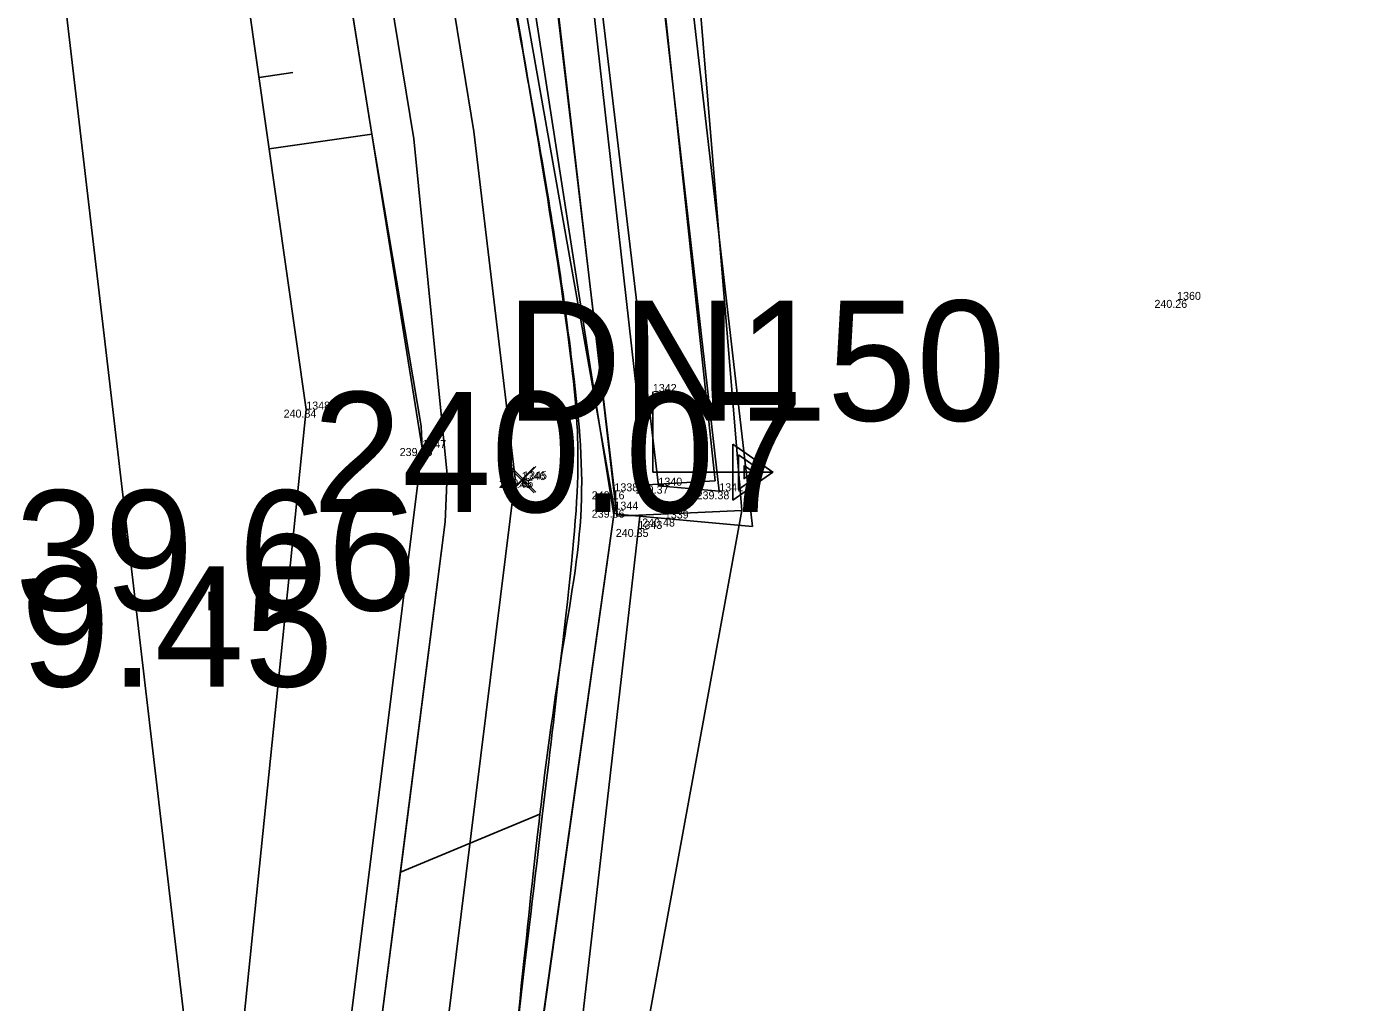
# Model space of a CAD drawing. Extents: x -555757 to -553364, y -1100723 to -1096439.
# Drawn here: x -553905.06 to -553888.24, y -1098914.94 to -1098902.76 of the extents above; entities that cross this region are included whole.
import ezdxf

# ---------------------------------------------------------------- set-up
doc = ezdxf.new("R2010")
doc.units = 0
for name, color, linetype in [('00_NÁVRH - 0.18 mm', 7, 'Continuous'), ('00_NÁVRH - 0.35 mm', 7, 'Continuous'), ('01_HLADINA', 7, 'Continuous'), ('Geodet. výšky - netisknuté', 7, 'Continuous'), ('HRANA$SVAHU', 7, 'Continuous'), ('HRANICE$PARCELY', 7, 'Continuous'), ('OSA$KOLEJI', 7, 'Continuous'), ('POPIS', 7, 'Continuous'), ('ROZHRANI', 7, 'Continuous'), ('SLUCKOV$$C$RA', 7, 'Continuous'), ('VODOVODY', 7, 'Continuous'), ('VYSKA_PODR_BOD', 7, 'Continuous'), ('VYSKOVE$SRAFY', 7, 'Continuous')]:
    doc.layers.add(name, color=color, linetype=linetype)

# ---------------------------------------------------------------- blocks, each defined once
blk = doc.blocks.new('POINT_DISPLAY')
blk.add_line((0, 0), (0, 0))
blk = doc.blocks.new('6$18')
at = {"layer": 'VODOVODY'}
for points in [[(0, 0), (0, -1), (1.5, -1)], [(1, -0.65), (1.5, -1), (1, -1.35), (1, -0.65)], [(1.07, -0.784), (1.378, -1), (1.07, -1.216), (1.07, -0.784)], [(1.14, -0.919), (1.256, -1), (1.14, -1.081), (1.14, -0.919)]]:
    blk.add_lwpolyline(points, dxfattribs=at)
blk = doc.blocks.new('BOD')
at = {"layer": 'POPIS'}
for p, q in [((-0.283, -0.283), (0.283, 0.283)), ((-0.283, 0.283), (0.283, -0.283))]:
    blk.add_line(p, q, dxfattribs=at)

msp = doc.modelspace()

# ---------------------------------------------------------------- linework, layer by layer
at = {"layer": '00_NÁVRH - 0.18 mm'}
for points in [[(-553947.788, -1099059.867), (-553935.377, -1099023.057), (-553925.589, -1098992.79), (-553914.105, -1098963.191), (-553902.24, -1098933.344), (-553901.606, -1098931.236), (-553900.811, -1098923.295), (-553898.96, -1098908.4), (-553899.478, -1098904.068), (-553900.725, -1098896.414), (-553901.4, -1098893.009), (-553901.337, -1098892.395), (-553901.104, -1098891.732), (-553884.458, -1098847.1)], [(-553942.062, -1099038.894), (-553935.99, -1099021.39), (-553928.935, -1098999.055), (-553926.84, -1098992.42), (-553922.458, -1098981.249), (-553916.003, -1098964.794), (-553911.939, -1098954.641), (-553909.255, -1098947.965), (-553903.25, -1098933.03), (-553903.005, -1098931.069), (-553900.12, -1098908.02), (-553900.136, -1098907.747), (-553900.75, -1098904.102), (-553902.469, -1098893.4), (-553902.5, -1098893.21), (-553902.5, -1098893.068), (-553902.439, -1098892.634), (-553902.302, -1098891.969), (-553902.077, -1098891.359), (-553899.834, -1098885.815), (-553893.94, -1098869.465), (-553889.919, -1098858.311), (-553887.458, -1098851.483), (-553885.715, -1098847.041)], [(-553946.39, -1099060.4), (-553933.906, -1099022.123), (-553924.31, -1098993.07), (-553913.795, -1098965.669), (-553901.23, -1098933.66), (-553900.818, -1098932.295), (-553900.55, -1098930.248), (-553899.67, -1098922.683), (-553897.726, -1098908.854), (-553898.025, -1098907), (-553899.515, -1098897.363), (-553900.336, -1098892.804), (-553883.522, -1098847.603)]]:
    msp.add_lwpolyline(points, dxfattribs=at)
at = {"layer": '00_NÁVRH - 0.35 mm'}
msp.add_lwpolyline([(-553948.493, -1099059.649), (-553935.545, -1099021.547), (-553926.445, -1098992.805), (-553915.734, -1098964.901), (-553914.927, -1098962.877), (-553903.079, -1098933.316), (-553902.406, -1098931.069), (-553901.65, -1098923.129), (-553899.834, -1098908.942), (-553899.809, -1098908.35), (-553900.227, -1098904.159), (-553901.487, -1098896.471), (-553902.129, -1098893.305), (-553902.102, -1098892.809), (-553902.038, -1098892.321), (-553901.906, -1098891.856), (-553885.171, -1098847.041)], dxfattribs=at)
msp.add_open_spline([(-553794.11, -1099299.314), (-553795.302, -1099298.083), (-553795.885, -1099297.697), (-553798.014, -1099296.378), (-553798.648, -1099296.009), (-553799.057, -1099295.868), (-553800.013, -1099295.626), (-553800.97, -1099295.434), (-553803.916, -1099294.978), (-553807.943, -1099294.404), (-553820.006, -1099292.714), (-553824.218, -1099292.087), (-553827.541, -1099291.556), (-553834.292, -1099290.18), (-553840, -1099289.072), (-553843.606, -1099288.311), (-553846.032, -1099287.854), (-553848.004, -1099287.449), (-553849.388, -1099287.281), (-553865.944, -1099285.252), (-553871.048, -1099284.805), (-553873.856, -1099284.514), (-553874.399, -1099284.43), (-553876.775, -1099283.969), (-553879.064, -1099283.332), (-553880.051, -1099283.031), (-553881.093, -1099282.392), (-553882.188, -1099281.754), (-553883.228, -1099281.083), (-553884.328, -1099279.969), (-553885.547, -1099278.713), (-553889.777, -1099274.4), (-553901.548, -1099262.428), (-553911.972, -1099251.719), (-553924.19, -1099239.3), (-553934.53, -1099228.739), (-553940.93, -1099222.274), (-553947.073, -1099216.541), (-553953.84, -1099210.491), (-553956.731, -1099207.941), (-553957.05, -1099207.628), (-553964.746, -1099199.605), (-553968.133, -1099195.981), (-553972.842, -1099191.048), (-553973.281, -1099190.444), (-553973.656, -1099189.74), (-553976.661, -1099181.556), (-553981.28, -1099169.188), (-553982.799, -1099164.023), (-553982.956, -1099163.184), (-553982.84, -1099162.204), (-553982.616, -1099160.636), (-553981.347, -1099154.446), (-553980.688, -1099150.992), (-553979.675, -1099146.656), (-553979.439, -1099145.68), (-553978.925, -1099144.071), (-553976.623, -1099137.958), (-553971.496, -1099124.445), (-553956.509, -1099083.004), (-553948.349, -1099063.109), (-553947.145, -1099060.166), (-553946.295, -1099057.429), (-553943.525, -1099049.31), (-553939.704, -1099037.846), (-553934.366, -1099021.961), (-553930.78, -1099011.15), (-553926.744, -1098998.785), (-553924.694, -1098992.816), (-553921.255, -1098983.982), (-553917.56, -1098974.667), (-553914.06, -1098965.564), (-553908.691, -1098951.909), (-553901.821, -1098934.804), (-553901.394, -1098933.668), (-553901.099, -1098932.553), (-553900.651, -1098929.575), (-553899.921, -1098923.604), (-553898.961, -1098915.482), (-553898.391, -1098910.691), (-553898.127, -1098908.396), (-553898.218, -1098907.183), (-553898.459, -1098905.433), (-553899.12, -1098901.506), (-553900.514, -1098893.561), (-553900.636, -1098892.888), (-553900.544, -1098892.328), (-553900.228, -1098891.412), (-553899.451, -1098889.266), (-553897.423, -1098883.769), (-553893.021, -1098871.924), (-553886.932, -1098855.681), (-553885.605, -1098852.197), (-553884.629, -1098849.656), (-553884.106, -1098848.151), (-553883.861, -1098847.39), (-553883.788, -1098846.997), (-553883.77, -1098846.594), (-553883.802, -1098846.171), (-553883.858, -1098845.819), (-553884.325, -1098844.246), (-553887.679, -1098834.274), (-553890.606, -1098825.191), (-553891.018, -1098823.527), (-553891.066, -1098823.121), (-553891.005, -1098822.697), (-553890.8, -1098821.707), (-553890.203, -1098818.823), (-553888.001, -1098807.301), (-553885.789, -1098795.251), (-553885.363, -1098792.934), (-553885.23, -1098792.173), (-553885.147, -1098791.711), (-553885.147, -1098791.302), (-553885.151, -1098791.006), (-553885.22, -1098790.609), (-553886.502, -1098784.837), (-553888.275, -1098776.483), (-553889.523, -1098771.371), (-553889.704, -1098770.489), (-553889.76, -1098769.236), (-553890.011, -1098761.77), (-553890.328, -1098747.9), (-553890.415, -1098743.459), (-553890.422, -1098742.114), (-553890.412, -1098741.338), (-553890.227, -1098740.638), (-553887.44, -1098731.802), (-553883.473, -1098718.833), (-553877.882, -1098700.91), (-553873.654, -1098687.07), (-553869.067, -1098673.807), (-553863.431, -1098657.948), (-553859.616, -1098647.384), (-553854.518, -1098632.992), (-553853.778, -1098630.91), (-553852.903, -1098628.215), (-553851.147, -1098622.78), (-553848.209, -1098613.648), (-553844.194, -1098601.116), (-553841.044, -1098590.723), (-553837.173, -1098577.952), (-553835.011, -1098570.679), (-553833.035, -1098564.139), (-553830.71, -1098556.281), (-553828.586, -1098548.945), (-553827.55, -1098545.495), (-553827.333, -1098544.629), (-553827.114, -1098543.601), (-553826.943, -1098542.73), (-553826.694, -1098541.466), (-553826.528, -1098540.348), (-553825.375, -1098531.946), (-553823.552, -1098519.221), (-553822.413, -1098510.953), (-553821.269, -1098503.56), (-553820.357, -1098496.716), (-553819.264, -1098489.108), (-553818.909, -1098486.041), (-553818.853, -1098485.532), (-553818.848, -1098485.156), (-553818.852, -1098484.16), (-553818.788, -1098477.885), (-553818.638, -1098467.214), (-553818.464, -1098454.698), (-553818.096, -1098433.157), (-553817.825, -1098416.015), (-553817.758, -1098409.125), (-553817.716, -1098406.971), (-553817.481, -1098400.257), (-553817.113, -1098388.412), (-553816.885, -1098378.571), (-553816.924, -1098376.341), (-553817.085, -1098375.505), (-553817.655, -1098372.671), (-553823.7, -1098343.15), (-553824.052, -1098341.595), (-553824.653, -1098340.008), (-553827.064, -1098334.584), (-553831.231, -1098324.895), (-553836.053, -1098314.241), (-553837.067, -1098312.263), (-553794.638, -1099298.639), (-553836.551, -1098313.247)], degree=3, dxfattribs=at)
at = {"layer": '01_HLADINA'}
for p, q in [((-553901.487, -1098896.471), (-553900.227, -1098904.159)), ((-553900.227, -1098904.159), (-553899.809, -1098908.35)), ((-553899.809, -1098908.35), (-553899.834, -1098908.942)), ((-553899.834, -1098908.942), (-553900.394, -1098913.317)), ((-553898.651, -1098912.59), (-553900.394, -1098913.317)), ((-553900.394, -1098913.317), (-553898.651, -1098912.59)), ((-553900.394, -1098913.317), (-553901.65, -1098923.129))]:
    msp.add_line(p, q, dxfattribs=at)
for points in [[(-553898.651, -1098912.59), (-553898.576, -1098911.957), (-553898.391, -1098910.559), (-553898.047, -1098908.761), (-553898.232, -1098906.998), (-553898.552, -1098904.701), (-553899.412, -1098900.167), (-553899.839, -1098895.974), (-553900.687, -1098892.928), (-553900.524, -1098892.19), (-553900.069, -1098891.007), (-553899.059, -1098888.138), (-553897.314, -1098883.489), (-553895.85, -1098879.544), (-553895.066, -1098877.43)], [(-553927.543, -1099001.209), (-553927.278, -1099000.401), (-553926.354, -1098997.594), (-553924.404, -1098991.798), (-553921.182, -1098983.816), (-553917.565, -1098974.761), (-553913.496, -1098964.024), (-553908.247, -1098950.734), (-553903.959, -1098940.137), (-553901.376, -1098933.695), (-553900.931, -1098931.954), (-553900.537, -1098928.578), (-553899.834, -1098922.891), (-553899.124, -1098917.226), (-553898.766, -1098913.554), (-553898.651, -1098912.59)]]:
    msp.add_open_spline(points, degree=3, dxfattribs=at)
at = {"layer": 'HRANA$SVAHU'}
for p, q in [((-553902.5, -1098893.21), (-553900.12, -1098908.02)), ((-553903.55, -1098893.61), (-553901.57, -1098907.54)), ((-553897.72, -1098908.79), (-553899.75, -1098897.36)), ((-553901.57, -1098907.54), (-553904.15, -1098932.71)), ((-553900.12, -1098908.02), (-553903.25, -1098933.03)), ((-553901.23, -1098933.66), (-553897.72, -1098908.79)), ((-553900.28, -1098933.97), (-553897.402, -1098908.871))]:
    msp.add_line(p, q, dxfattribs=at)
at = {"layer": 'HRANICE$PARCELY'}
for points in [[(-553905.08, -1098898.26), (-553904.36, -1098904.34), (-553902.71, -1098918.41), (-553903.57, -1098930.92), (-553917.2, -1098955.97), (-553924.62, -1098979.97), (-553942.06, -1099036.42), (-553962.73, -1099084.23), (-553967.43, -1099097.41), (-553978.87, -1099128.82), (-553980.54, -1099128.97)], [(-553900.5, -1098932.7), (-553896.13, -1098908.8), (-553896.91, -1098899.35)]]:
    msp.add_lwpolyline(points, dxfattribs=at)
at = {"layer": 'ROZHRANI'}
for p, q in [((-553899.031, -1098897.505), (-553897.687, -1098908.845)), ((-553898.48, -1098897.44), (-553897.17, -1098908.49)), ((-553896.41, -1098908.56), (-553897.46, -1098899.34)), ((-553895.993, -1098909.001), (-553897.08, -1098899.6)), ((-553897.17, -1098908.49), (-553896.41, -1098908.56)), ((-553897.687, -1098908.845), (-553895.993, -1098909.001))]:
    msp.add_line(p, q, dxfattribs=at)
at = {"layer": 'SLUCKOV$$C$RA'}
for p, q in [((-553899.03, -1098897.36), (-553897.69, -1098908.87)), ((-553897.31, -1098908.48), (-553898.57, -1098897.32)), ((-553897.43, -1098899.39), (-553896.46, -1098908.43)), ((-553896.46, -1098908.43), (-553897.31, -1098908.48)), ((-553897.69, -1098908.87), (-553896.13, -1098908.8))]:
    msp.add_line(p, q, dxfattribs=at)
at = {"layer": 'VYSKOVE$SRAFY'}
for p, q in [((-553902.16, -1098903.392), (-553901.737, -1098903.332)), ((-553902.033, -1098904.284), (-553900.75, -1098904.102))]:
    msp.add_line(p, q, dxfattribs=at)

# ---------------------------------------------------------------- block references
at = {"layer": 'POPIS', "xscale": 0.5624965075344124, "yscale": 0.5624965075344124}
for p in [(-553898.88, -1098908.42), (-553898.86, -1098908.41)]:
    msp.add_blockref('BOD', p, dxfattribs=at)
at = {"layer": 'ROZHRANI'}
for p in [(-553890.69, -1098906.17), (-553897.24, -1098907.32), (-553901.57, -1098907.54), (-553900.12, -1098908.02), (-553898.88, -1098908.42), (-553898.86, -1098908.41), (-553897.17, -1098908.49), (-553897.72, -1098908.56), (-553896.41, -1098908.56), (-553897.72, -1098908.79), (-553897.09, -1098908.9), (-553897.42, -1098909.03)]:
    msp.add_blockref('POINT_DISPLAY', p, dxfattribs=at)
at = {"layer": 'VODOVODY'}
msp.add_blockref('6$18', (-553897.24, -1098907.32), dxfattribs=at)

# ---------------------------------------------------------------- texts
at = {"layer": 'Geodet. výšky - netisknuté'}
for s, p in [('240.26', (-553890.973, -1098906.27)), ('240.84', (-553901.853, -1098907.64)), ('239.85', (-553900.403, -1098908.12)), ('239.45', (-553899.163, -1098908.52)), ('239.66', (-553899.143, -1098908.51)), ('239.37', (-553897.453, -1098908.59)), ('240.16', (-553898.003, -1098908.66)), ('239.38', (-553896.693, -1098908.66)), ('239.86', (-553898.003, -1098908.89)), ('240.48', (-553897.373, -1098909)), ('240.35', (-553897.703, -1098909.13))]:
    msp.add_text(s, height=0.1, dxfattribs=at).set_placement(p)
at = {"layer": 'OSA$KOLEJI'}
for s, p in [('1360', (-553890.69, -1098906.17)), ('1342', (-553897.24, -1098907.32)), ('1348', (-553901.57, -1098907.54)), ('1347', (-553900.12, -1098908.02)), ('1346', (-553898.88, -1098908.42)), ('1345', (-553898.86, -1098908.41)), ('1338', (-553897.72, -1098908.56)), ('1340', (-553897.17, -1098908.49)), ('1341', (-553896.41, -1098908.56)), ('1344', (-553897.72, -1098908.79)), ('1339', (-553897.09, -1098908.9)), ('1343', (-553897.42, -1098909.03))]:
    msp.add_text(s, height=0.1, dxfattribs=at).set_placement(p)
at = {"layer": 'POPIS'}
for s, p in [('DN150', (-553899.076, -1098907.679)), ('sediment 239.66', (-553915.021, -1098910.048)), ('dno 239.45', (-553911.271, -1098910.998))]:
    msp.add_text(s, height=1.5, dxfattribs=at).set_placement(p)
at = {"layer": 'VYSKA_PODR_BOD'}
msp.add_text('240.07', height=1.5, dxfattribs=at).set_placement((-553901.49, -1098908.82))

doc.saveas('drawing.dxf')
